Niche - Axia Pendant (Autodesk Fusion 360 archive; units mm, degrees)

design "Axia" references "Axia", "Luxe Single Pendant Cordset - 4ft Standard", "Niche - Chief Architect - Luxe Single Pendant Cordset"
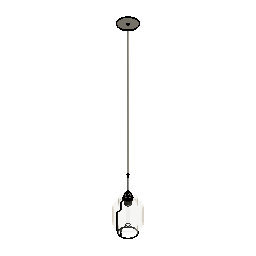
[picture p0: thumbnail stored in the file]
external_derived "ExternalDerived1" bodies "Axia"
external_derived "ExternalDerived2" bodies "Socket Body", "Shade Ring", "Shade Ring +Collar", "Socket", "Body1", "Metal Strain Relief", "Fabric Cord (1)", "Stem (Threaded)"
move "Move1"
align "Align1"
external_derived "ExternalDerived3" bodies "T9-Bulb"
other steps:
derived_base_feature "Derived Base Feature1" bodies "Body4", "Axia"
derived_base_feature "Derived Base Feature2" bodies "Socket Body", "Shade Ring", "Shade Ring +Collar", "Socket", "Body1", "Metal Strain Relief", "Fabric Cord (1)", "Stem (Threaded)"
derived_base_feature "Derived Base Feature3" bodies "T9-Bulb"
named bodies: "Body4", "Axia", "Socket Body", "Shade Ring", "Shade Ring +Collar", "Socket", "Body1", "Metal Strain Relief", "Fabric Cord (1)", "Stem (Threaded)", "Cap (Threaded)", "T9-Bulb"

design "Luxe Single Pendant Cordset - 4ft Standard" references "Luxe Canopy - Single Pendant Cordset"
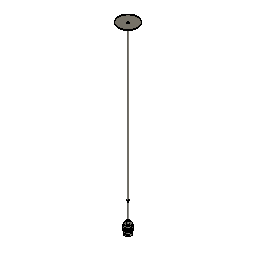
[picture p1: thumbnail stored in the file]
external_derived "ExternalDerived2" bodies "Cap (Threaded)"
move "Move1"
move "Move2"
offset_faces "OffsetFaces1" distance 1051.56
move "Move3"
move "Move4"
move "Move5"
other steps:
derived_base_feature "Derived Base Feature9" bodies "Socket Body", "Shade Ring", "Shade Ring +Collar", "Socket"
derived_base_feature "Derived Base Feature10" bodies "Body1"
derived_base_feature "Derived Base Feature12" bodies "Metal Strain Relief"
derived_base_feature "Derived Base Feature13" bodies "Fabric Cord (1)"
derived_base_feature "Derived Base Feature14" bodies "Stem (Threaded)"
derived_base_feature "Derived Base Feature15" bodies "Cap 9Threaded)", "Cap (Threaded)"
named bodies: "Socket Body", "Shade Ring", "Shade Ring +Collar", "Socket", "Metal Strain Relief", "Fabric Cord (1)", "Stem (Threaded)", "Cap 9Threaded)", "Body1", "Cap (Threaded)", "5M Set Screw"

design "Niche_Axia_Single_Pendant"
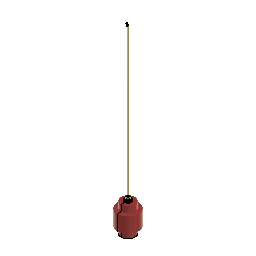
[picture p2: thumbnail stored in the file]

design "Luxe Canopy - Single Pendant Cordset" references "Luxe Cordset", "Canopy Mounting Bar", "M5 Set Screw", "Canopy Mounting Bar Screw", "Plastic Strain Relief"
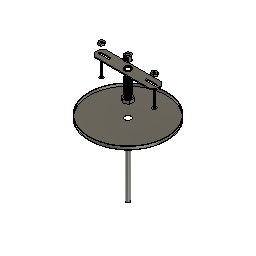
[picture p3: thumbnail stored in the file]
sketch "Sketch1" plane through (0, 0, 0) normal (0, 0, 1) x axis (1, 0, 0)
  circle C1 centre (0, 0) radius 63.5
  point P1 (0, 0)
  point P2 (0, 0)
  coincident P1 P2
  dimension "d1" diameter C1 = 127
extrude "Extrude1" new body sketch "Sketch1" along normal blind 5.08
shell "Shell1" innerThickness 0.762
hole "Hole1" HoleDepth 35.56 HoleDiameter 10.16 TipAngle 118
component_from_bodies "Body->Comp1"
component_insert "Component Insert1"
component_insert "Component Insert2"
component_insert "Component Insert3"
sketch "Sketch2" plane through (0, 0, 0) normal (0, 0, 1) x axis (1, 0, 0)
  circle C1 centre (0, 0) radius 3.175
  point P1 (0, 0)
  point P2 (0, 0)
  coincident P1 P2
  dimension "d8" diameter C1 = 6.35
extrude "Extrude2" new body sketch "Sketch2" along normal blind 127 and against normal blind 127 bodies "Fabric Cord"
component_insert "Component Insert4"
component_insert "Component Insert5"
position "Position1"
sketch "Sketch3" plane through (0, 0, 0.762) normal (0, 0, 1) x axis (-1, 0, 0)
  circle C1 centre (-0.0475, 0.2257) radius 5.08
  circle C2 centre (0, 0) radius 62.738
  circle C3 centre (0, 0) radius 4.826
  concentric C2 C3
  dimension "d13" diameter C3 = 9.652
extrude "Extrude3" new body sketch "Sketch3" profile of C3 along normal blind 25.4 bodies "Threaded Nipple"
shell "Shell2" innerThickness 1.27
thread "Thread1"
sketch "Sketch5" plane through (0, 0, 127) normal (0, 0, 1) x axis (-1, 0, 0)
  line L1 (-6.8191, 3.937) -> (0, 7.874)
  line L2 (-6.8191, -3.937) -> (-6.8191, 3.937)
  line L3 (0, -7.874) -> (-6.8191, -3.937)
  line L4 (6.8191, -3.937) -> (0, -7.874)
  line L5 (6.8191, 3.937) -> (6.8191, -3.937)
  line L6 (0, 7.874) -> (6.8191, 3.937)
  circle C1 centre (0, 0) radius 3.175
  point P2 (0, 0)
  point P9 (0, 0)
  point P3 (0, 7.874)
  coincident P2 P9
  dimension "d20" distance P3 P9 = 7.874
extrude "Extrude4" new body sketch "Sketch5" along normal blind 5.08 bodies "Hex Nut"
move "Move1"
thread "Thread2"
move "Move2" TranslateX 0 TranslateY 0 TranslateZ -55.88
move "Move3" TranslateX 0 TranslateY 0 TranslateZ 60.96
position "Position2"
sketch "Sketch6" plane through (0, 0, 0) normal (0, 0, 1) x axis (1, 0, 0)
  circle C1 centre (0, 0) radius 9.525
  point P1 (0, 0)
  point P2 (0, 0)
  coincident P1 P2
  dimension "d29" diameter C1 = 19.05
extrude "Extrude5" new body sketch "Sketch6" along normal blind 16.129 bodies "Metal Strain Relief"
move "Move4" TranslateX 0 TranslateY 0 TranslateZ -86.36
hole "Hole2" HoleDepth 10.16 HoleDiameter 5.08 TipAngle 118
hole "Hole3" HoleDepth 4.064 HoleDiameter 7.62 TipAngle 180
hole "Hole4" HoleDepth 12.192 HoleDiameter 9.144 TipAngle 180
thread "Thread3" ThreadOffset 0 ThreadLength 6.096
move "Move1" TranslateX 0 TranslateY 0 TranslateZ 68.58
move "Move5" TranslateX 0 TranslateY 0 TranslateZ 138.43
component_insert "Component Insert6"
external_derived "ExternalDerived1" bodies "5M Set Screw"
move "Move6" TranslateX 0 TranslateY 0 TranslateZ -185.42
copy_paste_bodies "CopyPasteBodies1"
move "Move7" TranslateX 0 TranslateY 0 TranslateZ -12.7
offset_faces "OffsetFaces1" distance -152.4
move "Move8"
component_from_bodies "Body->Comp2"
component_from_bodies "Body->Comp3"
component_from_bodies "Body->Comp4"
component_from_bodies "Body->Comp5"
hole "Hole1" HoleDepth 25.4 HoleDiameter 6.35 TipAngle 180
sketch "Sketch7" plane through (0, 0, 0) normal (0, 0, 1) x axis (1, 0, 0)
  line L1 (49.784, 3.9595) -> (52.07, 0)
  line L2 (45.212, 3.9595) -> (49.784, 3.9595)
  line L3 (42.926, 0) -> (45.212, 3.9595)
  line L4 (45.212, -3.9595) -> (42.926, 0)
  line L5 (49.784, -3.9595) -> (45.212, -3.9595)
  line L6 (52.07, 0) -> (49.784, -3.9595)
  point P2 (52.07, 0)
  point P8 (47.498, 0)
  dimension "d63" distance P2 P8 = 4.572
extrude "Extrude6" new body sketch "Sketch7" along normal blind 3.175 bodies "Mounting Hex Nut"
hole "Hole5" HoleDepth 25.4 HoleDiameter 3.81 TipAngle 180
thread "Thread4"
move "Move9"
component_from_bodies "Body->Comp6"
copy_paste "CopyPaste1"
move "Move10"
derived_base_feature "Derived Base Feature3" bodies "Stem (Threaded)", "Cap 9Threaded)"
move "Move11"
component_from_bodies "Body->Comp7"
component_from_bodies "Body->Comp8"
component_from_bodies "Body->Comp9"
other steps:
base_feature "Base Feature1"
base_feature "Base Feature1" bodies "Stem (Threaded)"
base_feature "Base Feature1" bodies "Cap 9Threaded)"
base_feature "Base Feature1" bodies "Fabric Cord"
base_feature "Base Feature1" bodies "Metal Strain Relief"
base_feature "Base Feature1" bodies "Mounting Hex Nut"
base_feature "Base Feature1" bodies "Hex Nut"
base_feature "Base Feature1" bodies "Fabric Cord (1)"
base_feature "Base Feature1" bodies "Threaded Nipple"
derived_base_feature "Derived Base Feature1" bodies "Socket Body", "Shade Ring", "Shade Ring +Collar", "Socket", "Rigid Stem"
derived_base_feature "Derived Base Feature2" bodies "5M Set Screw"
base_feature "Base Feature1" bodies "Fabric Cord", "Fabric Cord (1)"
create_component "CreateComponent1"
remove_body "RemoveBody1"
create_component "CreateComponent2"
remove_body "RemoveBody2"
create_component "CreateComponent3"
remove_body "RemoveBody3"
create_component "CreateComponent4"
remove_body "RemoveBody4"
create_component "CreateComponent5"
remove_body "RemoveBody5"
create_component "CreateComponent6"
remove_body "RemoveBody6"
create_component "CreateComponent7"
remove_body "RemoveBody7"
create_component "CreateComponent8"
remove_body "RemoveBody8"
create_component "CreateComponent9"
remove_body "RemoveBody9"
named bodies: "Fabric Cord", "Threaded Nipple", "Hex Nut", "Metal Strain Relief", "Socket Body", "Shade Ring", "Shade Ring +Collar", "Socket", "Rigid Stem", "5M Set Screw", "Fabric Cord (1)", "Mounting Hex Nut", "Stem (Threaded)", "Cap 9Threaded)"

design "Axia" references "Niche_Axia_Single_Pendant"
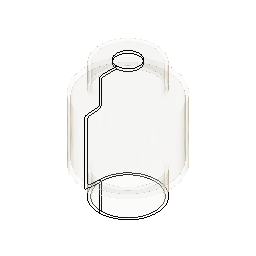
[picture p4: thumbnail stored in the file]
external_derived "ExternalDerived" bodies "Axia"
move "Move1"
hole "Hole1" HoleDepth 88.9 HoleDiameter 44.45 TipAngle 118
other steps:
derived_base_feature "Derived Base Feature" bodies "Axia"
named bodies: "Axia"

design "M5 Set Screw"
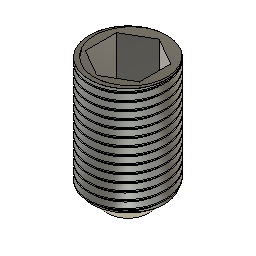
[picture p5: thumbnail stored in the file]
sketch "Sketch1" plane through (0, 0, 0) normal (0, 0, 1) x axis (1, 0, 0)
  circle C1 centre (0, 0) radius 2.5
  point P1 (0, 0)
  point P2 (0, 0)
  coincident P1 P2
  dimension "d1" diameter C1 = 5
extrude "Extrude1" new body sketch "Sketch1" along normal blind 8
sketch "Sketch2" plane through (0, 0, 8) normal (0, 0, 1) x axis (-1, 0, 0)
  line L1 (-1.7321, 1) -> (0, 2)
  line L2 (-1.7321, -1) -> (-1.7321, 1)
  line L3 (0, -2) -> (-1.7321, -1)
  line L4 (1.7321, -1) -> (0, -2)
  line L5 (1.7321, 1) -> (1.7321, -1)
  line L6 (0, 2) -> (1.7321, 1)
  circle C1 centre (0, 0) radius 2.5
  point P2 (0, 0)
  point P9 (0, 0)
  coincident P2 P9
extrude "Extrude2" cut sketch "Sketch2" profile of L1 L2 L3 L4 L5 L6 against normal blind 3
thread "Thread1" ThreadOffset 0.99 ThreadLength 7
chamfer "Chamfer1" distance 1.15

design "Luxe Cordset" references "M5 Set Screw"
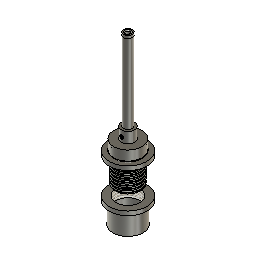
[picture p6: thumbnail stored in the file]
sketch "Sketch1" plane through (0, 0, 0) normal (0, 0, 1) x axis (1, 0, 0)
  circle C1 centre (0, 0) radius 20.6
  point P1 (0, 0)
  point P2 (0, 0)
  coincident P1 P2
  dimension "d11" diameter C1 = 41.2
extrude "Extrude1" new body sketch "Sketch1" along normal blind 14 bodies "Socket Body"
sketch "Sketch2" plane through (0, 0, 14) normal (0, 0, 1) x axis (-1, 0, 0)
  circle C1 centre (0, 0) radius 20.6
  circle C2 centre (0, 0) radius 9.6
  concentric C1 C2
  dimension "d3" diameter C2 = 19.2
extrude "Extrude2" add sketch "Sketch2" profile of C2 along normal blind 15.75
sketch "Sketch3" plane through (0, 0, 29.75) normal (0, 0, 1) x axis (-1, 0, 0)
  circle C1 centre (0, 0) radius 9.6
  circle C2 centre (0, 0) radius 5.75
  concentric C1 C2
  dimension "d6" diameter C2 = 11.5
extrude "Extrude3" new body sketch "Sketch3" profile of C2 along normal blind 114 bodies "Rigid Stem"
move "Move1"
sketch "Sketch4" plane through (0, 0, 203.75) normal (0, 0, 1) x axis (-1, 0, 0)
  circle C1 centre (0, 0) radius 5.75
  circle C2 centre (0, 0) radius 27.5
  dimension "d10" diameter C2 = 55
extrude "Extrude4" new body sketch "Sketch4" profile of C2 along normal blind 6 bodies "Shade Ring"
hole "Hole1" HoleDepth 25 HoleDiameter 42.75 TipAngle 118
sketch "Sketch5" plane through (0, 0, 0) normal (0, 0, 1) x axis (1, 0, 0)
  circle C1 centre (0, 0) radius 22
  point P1 (0, 0)
  point P2 (0, 0)
  coincident P1 P2
  dimension "d18" diameter C1 = 44
move "Move2"
copy_paste_bodies "CopyPasteBodies1"
move "Move3"
sketch "Sketch6" plane through (0, 0, 60) normal (0, 0, -1) x axis (1, 0, 0)
  circle C1 centre (0, 0) radius 20.6
  circle C2 centre (0, 0) radius 21.375
  circle C3 centre (0, 0) radius 20
  concentric C1 C2
  concentric C1 C3
  dimension "d21" diameter C2 = 42.75
  dimension "d24" diameter C3 = 40
cylinder_primitive "CylinderPrimitive1" Height 8 Diameter 42.75
thread "Thread1"
thread "Thread3"
hole "Hole2" HoleDepth 18 HoleDiameter 39 TipAngle 180
move "Move4"
move "Move5"
move "Move6"
hole "Hole3" HoleDepth 114 HoleDiameter 7.6 TipAngle 180
derived_base_feature "Derived Base Feature" bodies "Socket"
move "Move7"
scale "Scale1" ScaleX 1.2 ScaleY 1.2
move "Move8"
sketch "Sketch8" plane through (0, 0, -23.9827) normal (0, 0, -1) x axis (1, 0, 0)
  circle C1 centre (0, -0.036) radius 27.5
  circle C2 centre (0, -0.036) radius 22
  circle C3 centre (0, -0.036) radius 19.5
  dimension "d36" diameter C2 = 44
  dimension "d42" = -2.5
extrude "Extrude7" add sketch "Sketch8" profile of C2 C3 along normal blind 30
offset_faces "OffsetFaces1" distance 2.75
offset_faces "OffsetFaces2" distance -9
thread "Thread2"
move "Move9"
move "Move10"
move "Move11"
scale "Scale2" ScaleZ 1.2
move "Move12"
move "Move13"
move "Move14"
move "Move15"
move "Move16"
split_face "SplitFace1"
move "Move17"
move "Move18"
move "Move19"
move "Move20"
move "Move21"
move "Move22"
move "Move23"
move "Move24"
move "Move25"
move "Move26"
move "Move27"
thread "Thread4"
move "Move28"
move "Move29"
move "Move30"
hole "Hole4" HoleDepth 21 HoleDiameter 39.35 TipAngle 180
hole "Hole5" HoleDepth 9 HoleDiameter 5 TipAngle 180
move "Move31"
move "Move32"
hole "Hole6" HoleDepth 20 HoleDiameter 10 TipAngle 180
move_face "MoveFace3"
move "Move33"
move "Move34"
move "Move35"
move "Move36"
move "Move37"
thread "Thread5" ThreadOffset 0 ThreadLength 6
thread "Thread6" ThreadOffset 0 ThreadLength 6
move "Move38"
move "Move39"
move "Move40"
move "Move41"
component_insert "Component Insert"
thread "Thread7" ThreadOffset 0.5 ThreadLength 5.337
chamfer "Chamfer1" distance 0.5 distance 0.35
sketch "Sketch12" plane through (0, 0, 0) normal (0, 0, 1) x axis (1, 0, 0)
  circle C1 centre (0, 0) radius 6.35
  dimension "d60" diameter C1 = 12.7
extrude "Extrude8" new body sketch "Sketch12" along normal blind 115 bodies "Stem (Threaded)"
hole "Hole7" HoleDepth 115 HoleDiameter 9.65 TipAngle 118
thread "Thread8" ThreadOffset 0 ThreadLength 12.5
thread "Thread9" ThreadOffset 0 ThreadLength 12.5
sketch "Sketch13" plane through (0, 0, 0) normal (0, 0, 1) x axis (1, 0, 0)
  circle C1 centre (0, 0) radius 6.35
  point P1 (0, 0)
  point P2 (0, 0)
  coincident P1 P2
  dimension "d70" diameter C1 = 12.7
extrude "Extrude9" new body sketch "Sketch13" along normal blind 4 bodies "Cap 9Threaded)"
sketch "Sketch14" plane through (0, 0, 4) normal (0, 0, 1) x axis (-1, 0, 0)
  circle C1 centre (0, 0) radius 6.35
  circle C2 centre (0, 0) radius 4.5
  concentric C1 C2
  dimension "d73" diameter C2 = 9
extrude "Extrude10" add sketch "Sketch14" profile of C2 against normal blind 14
thread "Thread10"
hole "Hole8" HoleDepth 115 HoleDiameter 6.5 TipAngle 118 CSDiameter 9 CSAngle 90
move "Move42"
move "Move43"
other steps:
base_feature "Base Feature" bodies "Shade Ring +Collar"
named bodies: "Socket Body", "Shade Ring", "Shade Ring +Collar", "Socket", "Rigid Stem", "Stem (Threaded)", "Cap 9Threaded)"

design "Niche - Chief Architect - Luxe Single Pendant Cordset"
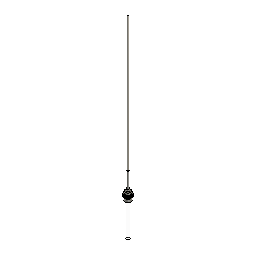
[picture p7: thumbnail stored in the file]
derived_base_feature "Derived Base Feature" bodies "Socket Body", "Shade Ring", "Shade Ring +Collar", "Socket", "Canopy", "Metal Strain Relief", "Fabric Cord (1)", "Stem (Threaded)"
remove_body "RemoveBody1"
remove_body "RemoveBody2"
split "Split1" bodies "Socket Body (1)"
remove_body "RemoveBody3"
align "Align1"
hole "Hole1" HoleDepth 19.05 HoleDiameter 8.89 TipAngle 118
combine "Combine1" bodies "Shade Ring"
split "Split2" bodies "Socket (1)"
remove_body "RemoveBody4"
split "Split3" bodies "Fabric Cord (1) (1)"
remove_body "RemoveBody5"
combine "Combine2" bodies "Socket Body"
align "Align2"
combine "Combine3" bodies "Metal Strain Relief"
sketch "Sketch1" plane through (0, 0, 0) normal (0, 1, 0) x axis (1, 0, 0)
  line L1 (13.1098, 24.9049) -> (-12.2902, 24.9049)
  line L2 (18.1898, 37.1766) -> (18.1898, 29.9849)
  line L3 (-17.3702, 29.9849) -> (-17.3702, 36.7132)
  line L4 (0, 132.969) -> (0, 24.9049)
  arc A1 centre (0, 86.36) radius 46.609 clockwise from (-22.6031, 45.5985) to (23.276, 45.979)
  arc A2 centre (-27.5302, 36.7132) radius 10.16 clockwise from (-22.6031, 45.5985) to (-17.3702, 36.7132)
  arc A3 centre (28.3498, 37.1766) radius 10.16 clockwise from (18.1898, 37.1766) to (23.276, 45.979)
  arc A4 centre (-12.2902, 29.9849) radius 5.08 clockwise from (-12.2902, 24.9049) to (-17.3702, 29.9849)
  arc A5 centre (13.1098, 29.9849) radius 5.08 clockwise from (18.1898, 29.9849) to (13.1098, 24.9049)
  point P5 (18.1898, 43.4469)
  point P3 (-17.3702, 24.9049)
  point P4 (18.1898, 24.9049)
  point P18 (0, 24.9049)
  point P19 (0, 132.969)
  horizontal L1
  vertical L2
  vertical L3
  tangent A1 A2
  tangent L3 A2
  coincident P5 L2
  coincident P5 A1
  tangent L2 A3
  tangent A1 A3
  equal A2 A3
  coincident P3 L1
  coincident P3 L3
  tangent L1 A4
  tangent L3 A4
  coincident P4 L1
  coincident P4 L2
  tangent L1 A5
  tangent L2 A5
  coincident L1 P18
  coincident A1 P19
  perpendicular L1 L4
  dimension "d4" diameter A1 = 93.218
  dimension "d5" distance P3 P4 = 35.56
  dimension "d6" distance P4 P5 = 18.542
  dimension "d7" radius A2 = 10.16
  dimension "d8" radius A4 = 5.08
  dimension "d9" radius A5 = 5.08
revolve "Revolve1" sketch "Sketch1" AlongAngle 360 bodies "G30-Bulb"
move "Move1"
sketch "Sketch2" plane through (0, 0, 0) normal (0, 1, 0) x axis (1, 0, 0)
  line L1 (12.7, 0) -> (-12.7, 0)
  line L2 (12.7, 152.4) -> (12.7, 0)
  line L3 (-12.7, 0) -> (-12.7, 152.4)
  line L4 (0, 165.1) -> (0, 0)
  arc A1 centre (0, 152.4) radius 12.7 clockwise from (-12.7, 152.4) to (12.7, 152.4)
  point P1 (0, 0)
  point P7 (0, 0)
  point P8 (0, 165.1)
  horizontal L1
  vertical L2
  vertical L3
  coincident P1 P7
  midpoint A1 P8
  perpendicular L1 L4
revolve "Revolve2" sketch "Sketch2" AlongAngle 360 bodies "T9-Bulb"
move "Move2"
sketch "Sketch3" plane through (0, 0, 0) normal (0, 1, 0) x axis (1, 0, 0)
  line L1 (12.7, 0) -> (-12.7, 0)
  line L2 (12.7, 254) -> (12.7, 0)
  line L3 (-12.7, 0) -> (-12.7, 254)
  line L4 (0, 266.7) -> (0, 0)
  arc A1 centre (0, 254) radius 12.7 clockwise from (-12.7, 254) to (12.7, 254)
  point P1 (0, 0)
  point P7 (0, 0)
  point P8 (0, 266.7)
  horizontal L1
  vertical L2
  vertical L3
  coincident P1 P7
  midpoint A1 P8
  perpendicular L1 L4
revolve "Revolve3" sketch "Sketch3" AlongAngle 360 bodies "T8-Bulb"
move "Move3"
move "Move4"
move "Move5"
sketch "Sketch4" plane through (0, 0, 0) normal (0, 1, 0) x axis (1, 0, 0)
  line L1 (15.875, -8.763) -> (-15.875, -8.763)
  line L2 (15.875, 22.987) -> (15.875, -8.763)
  line L3 (-15.875, 22.987) -> (15.875, 22.987)
  line L4 (-15.875, -8.763) -> (-15.875, 22.987)
  line L5 (0, 22.987) -> (0, -8.763)
  point P6 (0, -8.763)
  point P7 (0, 22.987)
  point P2 (-15.875, -8.763)
  point P3 (15.875, -8.763)
  point P5 (-15.875, 22.987)
  horizontal L1
  vertical L2
  horizontal L3
  vertical L4
  midpoint L1 P6
  midpoint L3 P7
  dimension "d13" distance P2 P3 = 31.75
  dimension "d14" distance P2 P5 = 31.75
revolve "Revolve4" sketch "Sketch4" AlongAngle 360 bodies "Bulb Extender"
move "Move6"
sketch "Sketch5" plane through (0, 0, 0) normal (0, 1, 0) x axis (1, 0, 0)
  line L1 (-12.7, 35.56) -> (12.7, 35.56)
  line L2 (-12.7, 5.08) -> (-12.7, 35.56)
  line L3 (12.7, 5.08) -> (-12.7, 5.08)
  line L4 (12.7, 35.56) -> (12.7, 5.08)
  line L5 (-12.7, 5.08) -> (12.7, 35.56)
  line L6 (12.7, 5.08) -> (-12.7, 35.56)
  line L7 (0, 35.56) -> (0, 5.08)
  point P6 (0, 20.32)
  point P7 (0, 5.08)
  point P8 (0, 35.56)
  horizontal L1
  perpendicular L1 L2
  parallel L1 L3
  parallel L2 L4
  coincident L5 P6
  coincident L6 P6
  midpoint L3 P7
  midpoint L1 P8
revolve "Revolve5" sketch "Sketch5" AlongAngle 360 bodies "Y-Spliter"
sketch "Sketch6" plane through (0, 0, 0) normal (0, 1, 0) x axis (1, 0, 0)
  line L1 (-55.88, 64.9514) -> (-21.59, 64.9514)
  line L2 (-55.88, 35.7414) -> (-55.88, 64.9514)
  line L3 (-21.59, 35.7414) -> (-55.88, 35.7414)
  line L4 (-21.59, 64.9514) -> (-21.59, 35.7414)
  line L5 (-55.88, 35.7414) -> (-21.59, 64.9514)
  line L6 (-21.59, 35.7414) -> (-55.88, 64.9514)
  line L7 (-38.735, 64.9514) -> (-38.735, 35.7414)
  point P6 (-38.735, 50.3464)
  point P7 (-38.735, 35.7414)
  point P8 (-38.735, 64.9514)
  point P4 (-55.88, 35.7414)
  point P5 (-21.59, 35.7414)
  point P2 (-21.59, 64.9514)
  horizontal L1
  perpendicular L1 L2
  parallel L1 L3
  parallel L2 L4
  coincident L5 P6
  coincident L6 P6
  midpoint L3 P7
  midpoint L1 P8
  dimension "d17" distance P4 P5 = 34.29
  dimension "d18" distance P2 P5 = 29.21
revolve "Revolve6" sketch "Sketch6" AlongAngle 360
chamfer "Chamfer1" distance 7.62
move "Move7"
mirror "Mirror1" mirrorStitchTolerance 0.1016
move "Move8"
combine "Combine4"
move "Move9"
sketch "Sketch7" plane through (0, 0, 0) normal (0, 1, 0) x axis (1, 0, 0)
  line L1 (-15.24, 40.64) -> (-15.24, 48.1816)
  line L2 (12.7, 38.1) -> (-12.7, 38.1)
  line L3 (15.24, 48.1816) -> (15.24, 40.64)
  line L4 (0, 100.1623) -> (0, 38.1)
  arc A1 centre (0, 76.2) radius 23.9623 clockwise from (-19.7282, 62.5988) to (19.7282, 62.5988)
  arc A2 centre (-40.64, 48.1816) radius 25.4 clockwise from (-19.7282, 62.5988) to (-15.24, 48.1816)
  arc A3 centre (40.64, 48.1816) radius 25.4 clockwise from (15.24, 48.1816) to (19.7282, 62.5988)
  arc A4 centre (-12.7, 40.64) radius 2.54 clockwise from (-12.7, 38.1) to (-15.24, 40.64)
  arc A5 centre (12.7, 40.64) radius 2.54 clockwise from (15.24, 40.64) to (12.7, 38.1)
  point P15 (0, 38.1)
  point P16 (0, 100.1623)
  parallel L1 L3
  tangent A1 A2
  tangent L1 A2
  tangent A1 A3
  tangent L3 A3
  tangent L1 A4
  tangent L2 A4
  tangent L2 A5
  tangent L3 A5
  midpoint L2 P15
  midpoint A1 P16
  perpendicular L2 L4
  dimension "d23" radius A2 = 25.4
  dimension "d24" radius A3 = 25.4
  dimension "d25" radius A4 = 2.54
  dimension "d26" radius A5 = 2.54
revolve "Revolve7" sketch "Sketch7" AlongAngle 360 bodies "A15-Bulb"
move "Move10"
copy_paste_bodies "CopyPasteBodies1"
copy_paste_bodies "CopyPasteBodies2"
move "Move11"
mirror "Mirror2" mirrorStitchTolerance 0.1016 bodies "A15-Bulb (1) (1)"
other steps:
base_feature "Base Feature1" bodies "Y-Spliter", "Bulb Extender", "Y-Spliter (1)", "Bulb Extender (1)"
base_feature "Base Feature2" bodies "A15-Bulb", "A15-Bulb (1)"
named bodies: "Socket Body", "Shade Ring", "Shade Ring +Collar", "Socket", "Canopy", "Metal Strain Relief", "Fabric Cord (1)", "Stem (Threaded)", "Adapter", "5M Set Screw", "Body1 (1)", "Socket Body (1)", "Socket (1)", "Fabric Cord (1) (1)", "G30-Bulb", "T9-Bulb", "T8-Bulb", "Bulb Extender", "Y-Spliter", "A15-Bulb", "Y-Spliter (1)", "Bulb Extender (1)", "A15-Bulb (1)", "A15-Bulb (1) (1)"

design "Plastic Strain Relief"
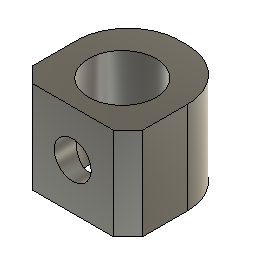
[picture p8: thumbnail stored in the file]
base_feature "Base Feature" bodies "strainrelief"
named bodies: "strainrelief"

design "Canopy Mounting Bar Screw"
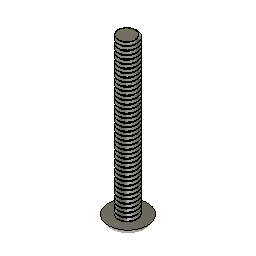
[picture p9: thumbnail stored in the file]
base_feature "Base Feature" bodies "screw1"
named bodies: "screw1"

design "Canopy Mounting Bar"
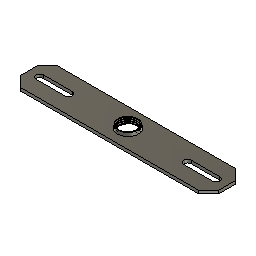
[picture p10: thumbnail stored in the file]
base_feature "Base Feature" bodies "mountingbar"
named bodies: "mountingbar"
